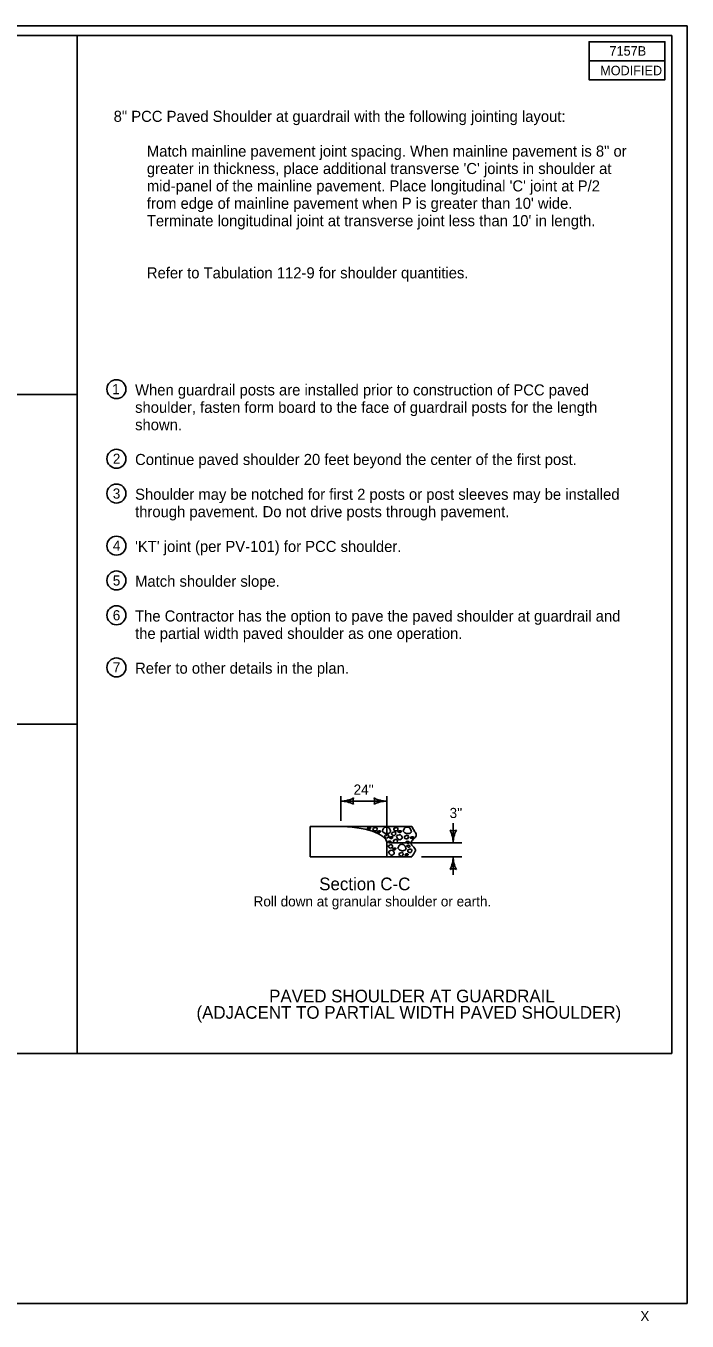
# Model space of a CAD drawing. Extents: x 9538 to 81668, y 7600 to 11751.
# Drawn here: x 23022 to 24068, y 7896 to 9944 of the extents above; entities that cross this region are included whole.
import ezdxf

# ---------------------------------------------------------------- set-up
doc = ezdxf.new("R2010")
doc.units = 0
for name, color, linetype in [('Default', 7, 'Continuous'), ('DsnShtMinorGrid12', 7, 'Continuous'), ('DsnShtMinorGrid13', 7, 'Continuous'), ('dsnStdBlockNotModified', 7, 'Continuous'), ('dsnStdCells', 7, 'Continuous'), ('dsnStdDimension', 7, 'Continuous'), ('dsnStdNameDate', 7, 'Continuous'), ('dsnStdNote', 7, 'Continuous'), ('dsnStdShading', 7, 'Continuous'), ('dsnStdTable', 7, 'Continuous'), ('Level 9', 7, 'Continuous')]:
    doc.layers.add(name, color=color, linetype=linetype)

msp = doc.modelspace()

# ---------------------------------------------------------------- linework, layer by layer
at = {"layer": 'Default'}
msp.add_lwpolyline([(20932.5, 9944), (24067.5, 9944), (24067.5, 7924), (20932.5, 7924)], close=True, dxfattribs=at)
at = {"layer": 'DsnShtMinorGrid12'}
for points in [[(23564.3, 8674.1), (23565.1, 8673.9), (23565.7, 8673.9), (23568.1, 8676.3), (23564.1, 8677.1), (23560.6, 8675), (23563.4, 8674.3), (23564.3, 8674.1)], [(23570.7, 8674.6), (23570.8, 8675.1), (23571.1, 8675), (23575.7, 8677.6), (23578.1, 8674.4), (23576, 8670.4), (23570.9, 8671.5), (23570.7, 8674), (23570.7, 8674.6)], [(23579.9, 8668.6), (23580.8, 8668.4), (23581.3, 8668.4), (23583.7, 8670.8), (23579.7, 8671.6), (23576.2, 8669.5), (23579.1, 8668.7), (23579.9, 8668.6)], [(23585.6, 8670.8), (23585.3, 8671.3), (23585.9, 8670.9), (23587.7, 8677.4), (23596, 8677.6), (23598.7, 8670.4), (23599, 8669.6), (23594.2, 8665.8), (23587.5, 8668), (23585.9, 8670.3), (23585.6, 8670.8)], [(23589.1, 8663.3), (23589.1, 8663.9), (23589.5, 8663.7), (23594.1, 8666.4), (23596.5, 8663.2), (23594.3, 8659.2), (23589.2, 8660.2), (23589.1, 8662.7), (23589.1, 8663.3)], [(23600.1, 8667.4), (23600.2, 8668), (23600.5, 8667.8), (23605.1, 8670.5), (23607.5, 8667.3), (23605.3, 8663.2), (23600.3, 8664.3), (23600.1, 8666.8), (23600.1, 8667.4)], [(23603.7, 8674.6), (23603.7, 8675.1), (23604.1, 8675), (23608.6, 8677.6), (23611, 8674.4), (23608.9, 8670.4), (23603.8, 8671.5), (23603.6, 8674), (23603.7, 8674.6)], [(23608.2, 8661.4), (23607.6, 8662.5), (23607.8, 8662.9), (23612.4, 8665.8), (23616.4, 8664), (23617.5, 8658.6), (23611.3, 8655.9), (23608.8, 8660.2), (23608.2, 8661.4)], [(23612.9, 8668.6), (23613.7, 8668.4), (23614.2, 8668.4), (23616.7, 8670.8), (23612.6, 8671.6), (23609.2, 8669.5), (23612, 8668.7), (23612.9, 8668.6)], [(23618.5, 8670.8), (23618.3, 8671.3), (23618.8, 8670.9), (23620.7, 8677.4), (23629, 8677.6), (23631.7, 8670.4), (23631.9, 8669.6), (23627.1, 8665.8), (23620.4, 8668), (23618.8, 8670.3), (23618.5, 8670.8)], [(23620.4, 8662), (23620.4, 8662.6), (23620.8, 8662.4), (23625.4, 8665.1), (23627.8, 8661.9), (23625.6, 8657.9), (23620.5, 8658.9), (23620.4, 8661.4), (23620.4, 8662)], [(23594.5, 8653.6), (23594.1, 8654.1), (23594.4, 8654.5), (23598.7, 8655.8), (23600.1, 8652.3), (23596.9, 8651.5), (23594.9, 8653.2), (23594.5, 8653.6)], [(23595.2, 8647.4), (23595.3, 8648), (23595.6, 8647.8), (23600.2, 8650.5), (23602.6, 8647.3), (23600.5, 8643.3), (23595.4, 8644.3), (23595.2, 8646.8), (23595.2, 8647.4)], [(23599.2, 8659.3), (23600.1, 8659.1), (23600.6, 8659.1), (23603, 8661.6), (23599, 8662.4), (23595.5, 8660.2), (23598.4, 8659.5), (23599.2, 8659.3)], [(23604.4, 8641.4), (23605.3, 8641.3), (23605.8, 8641.3), (23608.2, 8643.7), (23604.2, 8644.5), (23600.7, 8642.3), (23603.6, 8641.6), (23604.4, 8641.4)], [(23603, 8655.6), (23603, 8656.2), (23603.4, 8656), (23607.9, 8658.7), (23610.4, 8655.4), (23608.2, 8651.4), (23603.1, 8652.5), (23602.9, 8655), (23603, 8655.6)], [(23610.1, 8643.7), (23609.8, 8644.2), (23610.4, 8643.8), (23612.3, 8650.2), (23620.6, 8650.5), (23623.2, 8643.3), (23623.5, 8642.5), (23618.7, 8638.7), (23612, 8640.9), (23610.4, 8643.2), (23610.1, 8643.7)], [(23623.1, 8653.2), (23622.7, 8653.7), (23623.1, 8654.1), (23627.4, 8655.4), (23628.7, 8651.9), (23625.5, 8651.1), (23623.5, 8652.7), (23623.1, 8653.2)], [(23624.4, 8647.1), (23624, 8647.6), (23624.4, 8648), (23628.7, 8649.3), (23630, 8645.8), (23626.8, 8645), (23624.8, 8646.6), (23624.4, 8647.1)], [(23632.1, 8659.3), (23633, 8659.1), (23633.5, 8659.1), (23635.9, 8661.6), (23631.9, 8662.4), (23628.4, 8660.2), (23631.3, 8659.5), (23632.1, 8659.3)], [(23595.7, 8636.9), (23595.1, 8638), (23595.3, 8638.4), (23599.8, 8641.3), (23603.8, 8639.4), (23604.9, 8634.1), (23598.7, 8631.4), (23596.2, 8635.7), (23595.7, 8636.9)], [(23612, 8634.9), (23612, 8635.5), (23612.4, 8635.3), (23616.9, 8638), (23619.4, 8634.7), (23617.2, 8630.7), (23612.1, 8631.8), (23611.9, 8634.3), (23612, 8634.9)], [(23623.7, 8632.2), (23624.6, 8632), (23625.1, 8632), (23627.5, 8634.4), (23623.5, 8635.2), (23620, 8633.1), (23622.9, 8632.4), (23623.7, 8632.2)], [(23625.6, 8640.3), (23625.6, 8640.9), (23626, 8640.7), (23630.5, 8643.4), (23632.9, 8640.2), (23630.8, 8636.2), (23625.7, 8637.2), (23625.5, 8639.7), (23625.6, 8640.3)]]:
    msp.add_open_spline(points, degree=3, dxfattribs=at)
at = {"layer": 'DsnShtMinorGrid13'}
for centre in [(23164.9, 9369.6), (23164.9, 9259.6), (23164.9, 9204.6), (23164.9, 9122.1), (23164.9, 9067.1), (23164.9, 9012.1), (23164.9, 8929.6)]:
    msp.add_circle(centre, 15, dxfattribs=at)
at = {"layer": 'dsnStdCells'}
for p, q in [((23514.7, 8678.3), (23471.6, 8678.3)), ((23471.6, 8678.3), (23471.6, 8630.3)), ((23592.5, 8630.3), (23592.5, 8652.1)), ((23471.6, 8630.3), (23592.5, 8630.3))]:
    msp.add_line(p, q, dxfattribs=at)
msp.add_lwpolyline([(23514.7, 8678.3), (23514.7, 8678.3)], dxfattribs=at)
msp.add_ellipse((23514.7, 8652.1), major_axis=(77.9, 0), ratio=0.335273, start_param=0, end_param=1.570796, dxfattribs=at)
at = {"layer": 'dsnStdDimension'}
for p, q in [((23520, 8686.8), (23520, 8726.2)), ((23592.5, 8726.2), (23592.5, 8662.7)), ((23520, 8718.2), (23592.5, 8718.2)), ((23697.6, 8683.1), (23697.6, 8652.1)), ((23599.4, 8652.1), (23711.4, 8652.1)), ((23647.3, 8630.3), (23711.4, 8630.3)), ((23697.6, 8630.3), (23697.6, 8601.7))]:
    msp.add_line(p, q, dxfattribs=at)
for centre, radius, start, end in [((23520, 8760.7), 42.5, 270, 298.0725), ((23520, 8675.7), 42.5, 61.9275, 90), ((23555.6, 8718.2), 16.4, 162.2666, 197.7334), ((23556.9, 8718.2), 16.4, 342.2666, 17.7334), ((23592.5, 8760.7), 42.5, 241.9275, 270), ((23592.5, 8675.7), 42.5, 90, 118.0725), ((23697.6, 8687.8), 16.4, 252.2666, 287.7334), ((23655.1, 8652.1), 42.5, 0, 28.0725), ((23740.1, 8652.1), 42.5, 151.9275, 180), ((23655.1, 8630.3), 42.5, 331.9275, 360), ((23740.1, 8630.3), 42.5, 180, 208.0725), ((23697.6, 8594.7), 16.4, 72.2666, 107.7334)]:
    msp.add_arc(centre, radius, start, end, dxfattribs=at)
at = {"layer": 'dsnStdNameDate'}
for p, q in [((23103.1, 8319), (23103.1, 9929)), ((23103.1, 9361), (20947.5, 9361)), ((23103.1, 8840), (20947.5, 8840))]:
    msp.add_line(p, q, dxfattribs=at)
at = {"layer": 'dsnStdShading'}
for p, q in [((20947.5, 9929), (24043.2, 9929)), ((24043.2, 9929), (24043.2, 8319)), ((20947.5, 8319), (24043.2, 8319))]:
    msp.add_line(p, q, dxfattribs=at)
at = {"layer": 'dsnStdTable'}
for p, q in [((24043.2, 9929), (24043.2, 9929)), ((23471.6, 8678.3), (23471.6, 8630.3)), ((23471.6, 8678.3), (23514.7, 8678.3)), ((23514.7, 8678.3), (23632.4, 8678.3)), ((23592.5, 8652.1), (23592.5, 8630.3)), ((23471.6, 8630.3), (23592.5, 8630.3)), ((23592.5, 8630.3), (23632.4, 8630.3))]:
    msp.add_line(p, q, dxfattribs=at)
msp.add_lwpolyline([(24032.4, 9919), (24032.4, 9859), (23912.6, 9859), (23912.6, 9919), (24032.4, 9919), (24032.4, 9889), (23912.6, 9889)], dxfattribs=at)
msp.add_ellipse((23514.7, 8652.1), major_axis=(77.9, 0), ratio=0.335273, start_param=0, end_param=1.570796, dxfattribs=at)
msp.add_spline([(23632.4, 8678.3), (23633.8, 8675.1), (23635.7, 8671.9), (23637.5, 8668.9), (23639, 8665.8), (23639.1, 8664.1), (23638.4, 8662.3), (23635.6, 8658.8), (23632.4, 8655.3), (23631.3, 8653.6), (23631, 8652.7), (23630.8, 8651.8), (23630.9, 8651.4), (23631.2, 8650.2), (23632.2, 8648.7), (23635.1, 8645.5), (23637.6, 8642.3), (23638.1, 8640.7), (23638, 8639.9), (23637.9, 8639.5), (23637.7, 8639.1), (23632.4, 8630.4)], degree=3, dxfattribs=at)

# ---------------------------------------------------------------- texts
at = {"layer": 'DsnShtMinorGrid13'}
for s, height, p in [('8" PCC Paved Shoulder at guardrail with the following jointing layout:', 17.5, (23160.6, 9792.3)), ('Match mainline pavement joint spacing. When mainline pavement is 8" or ', 17.5, (23213.1, 9737.3)), ("greater in thickness, place additional transverse 'C' joints in shoulder at ", 17.5, (23213.1, 9709.8)), ("mid-panel of the mainline pavement. Place longitudinal 'C' joint at P/2 ", 17.5, (23213.1, 9682.3)), ("from edge of mainline pavement when P is greater than 10' wide. ", 17.5, (23213.1, 9654.8)), ("Terminate longitudinal joint at transverse joint less than 10' in length.", 17.5, (23213.1, 9627.3)), ('Refer to Tabulation 112-9 for shoulder quantities.', 17.5, (23213.1, 9544.8)), ('1', 16, (23158.2, 9361.6)), ('When guardrail posts are installed prior to construction of PCC paved ', 17.5, (23194.5, 9359.7)), ('shoulder, fasten form board to the face of guardrail posts for the length ', 17.5, (23194.5, 9332.2)), ('shown.', 17.5, (23194.5, 9304.7)), ('2', 16, (23159.3, 9251.6)), ('Continue paved shoulder 20 feet beyond the center of the first post.', 17.5, (23194.5, 9249.7)), ('3', 16, (23159.2, 9196.6)), ('Shoulder may be notched for first 2 posts or post sleeves may be installed ', 17.5, (23194.5, 9194.7)), ('through pavement. Do not drive posts through pavement.', 17.5, (23194.5, 9167.2)), ('4', 16, (23159.3, 9114.1)), ("'KT' joint (per PV-101) for PCC shoulder.", 17.5, (23194.5, 9112.2)), ('5', 16, (23159.2, 9059.1)), ('Match shoulder slope.', 17.5, (23194.5, 9057.2)), ('6', 16, (23159.2, 9004.1)), ('The Contractor has the option to pave the paved shoulder at guardrail and ', 17.5, (23194.5, 9002.2)), ('the partial width paved shoulder as one operation.', 17.5, (23194.5, 8974.7)), ('7', 16, (23159.2, 8921.6)), ('Refer to other details in the plan.', 17.5, (23194.5, 8919.7))]:
    msp.add_text(s, height=height, dxfattribs=at).set_placement(p)
at = {"layer": 'dsnStdBlockNotModified'}
msp.add_text('X', height=16, dxfattribs=at).set_placement((23993.6, 7896))
at = {"layer": 'dsnStdDimension'}
for s, p in [("24''", (23540.1, 8728.5)), ("3'' ", (23691.9, 8691.5))]:
    msp.add_text(s, height=16, dxfattribs=at).set_placement(p)
at = {"layer": 'dsnStdNote'}
for s, height, p in [('Section C-C', 20, (23485.7, 8577.3)), ('Roll down at granular shoulder or earth.', 16, (23381.9, 8551.7)), ('PAVED SHOULDER AT GUARDRAIL', 20, (23406.5, 8400)), ('(ADJACENT TO PARTIAL WIDTH PAVED SHOULDER)', 20, (23291.6, 8374.1))]:
    msp.add_text(s, height=height, dxfattribs=at).set_placement(p)
at = {"layer": 'Level 9'}
for s, p in [('7157B', (23944.8, 9897)), ('MODIFIED', (23930, 9866))]:
    msp.add_text(s, height=15, dxfattribs=at).set_placement(p)

doc.saveas('drawing.dxf')
